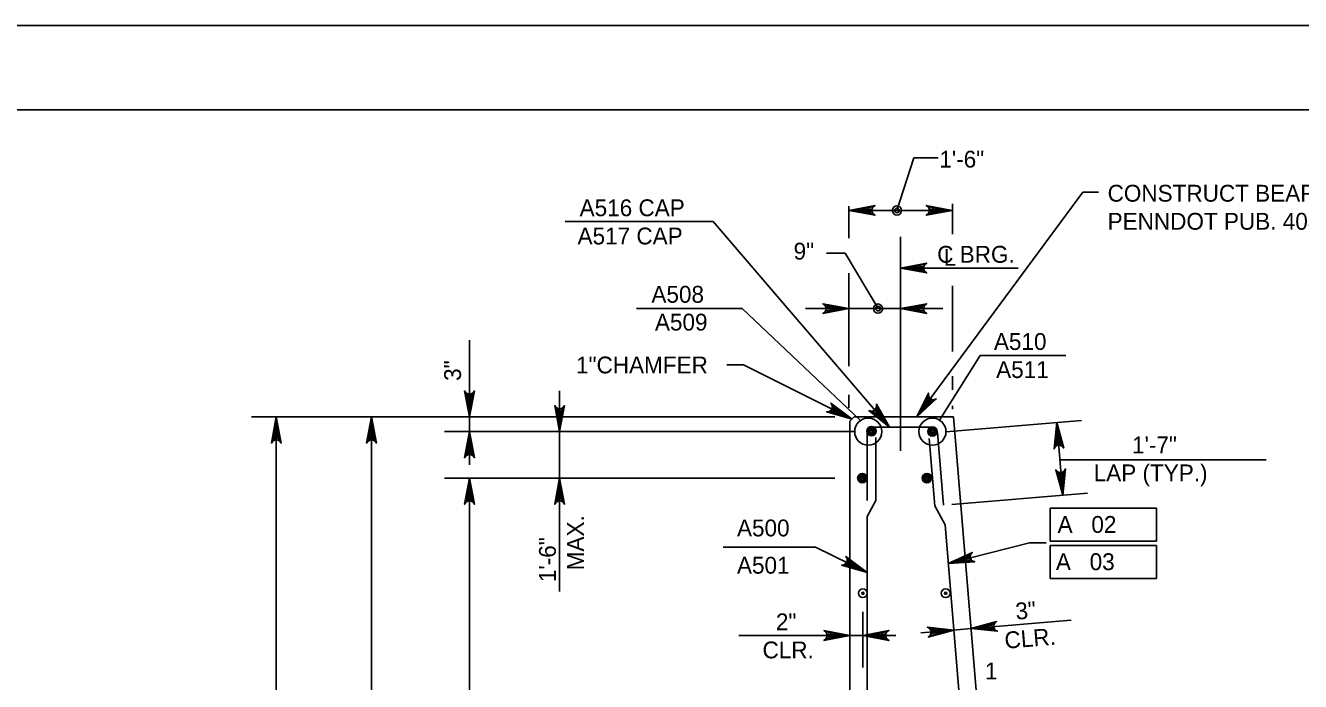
# Model space of a CAD drawing. Extents: x 638255 to 640306, y 296059 to 298435.
# Drawn here: x 638961.1 to 639188.3, y 298318.6 to 298435.5 of the extents above; entities that cross this region are included whole.
import ezdxf

# ---------------------------------------------------------------- set-up
doc = ezdxf.new("R2010")
doc.units = 0
for name, color, linetype in [('2', 7, 'Continuous'), ('3', 7, 'Continuous'), ('Level 3', 7, 'Continuous'), ('Level 4', 7, 'Continuous'), ('Level 5', 7, 'Continuous'), ('Level 9', 7, 'Continuous'), ('PLT-BNDY', 7, 'Continuous')]:
    doc.layers.add(name, color=color, linetype=linetype)

# ---------------------------------------------------------------- blocks, each defined once
blk = doc.blocks.new('B')
at = {"layer": '3'}
blk.add_circle((0, 0), 0.16, dxfattribs=at)
for start, end in [(0, 180), (180, 0)]:
    blk.add_arc((0, 0), 0.0391, start, end, dxfattribs=at)

msp = doc.modelspace()

# ---------------------------------------------------------------- linework, layer by layer
at = {"layer": '2'}
msp.add_line((638475.46, 298420.46), (639261.46, 298420.46), dxfattribs=at)
at = {"layer": 'Level 3'}
for p, q in [((639119.44, 298411.85), (639116.41, 298402.51)), ((639119.44, 298411.85), (639123.73, 298411.85)), ((639119.95, 298365.71), (639149.54, 298405.75)), ((639149.54, 298405.75), (639152.29, 298405.75)), ((639107.85, 298397.56), (639107.85, 298403.25)), ((639107.85, 298402.51), (639126.27, 298402.51)), ((639126.27, 298402.51), (639126.27, 298402.51)), ((639126.28, 298398.27), (639126.28, 298403.68)), ((639083.67, 298400.56), (639057.3, 298400.56)), ((639115.09, 298363.89), (639083.67, 298400.56)), ((639117.06, 298359.67), (639117.06, 298397.79)), ((639103.85, 298394.89), (639107.19, 298394.89)), ((639113.03, 298385.01), (639107.19, 298394.89)), ((639107.85, 298374.74), (639107.85, 298391.33)), ((639117.06, 298392.23), (639137.99, 298392.23)), ((639107.85, 298385.03), (639107.85, 298389.72)), ((639107.85, 298386.42), (639107.85, 298389.43)), ((639126.28, 298377.35), (639126.28, 298389.06)), ((639124.58, 298385.01), (639100.13, 298385.01)), ((639040.23, 298363.1), (639040.23, 298379.42)), ((639089.04, 298375), (639086.1, 298375)), ((639108.42, 298365.33), (639089.04, 298375)), ((639126.28, 298370.55), (639126.28, 298372.97)), ((639040.23, 298365.71), (639040.23, 298371.6)), ((639056.3, 298370.39), (639056.3, 298334.62)), ((639107.85, 298367.32), (639107.85, 298369.63)), ((639126.28, 298367.09), (639126.28, 298367.67)), ((639035.11, 298365.71), (639001.39, 298365.71)), ((639005.81, 298204.3), (639005.81, 298365.71)), ((639105.34, 298365.71), (639018.36, 298365.71)), ((639022.78, 298365.71), (639022.78, 298297.2)), ((639022.78, 298365.71), (639022.78, 298365.71)), ((639053.45, 298365.71), (639035.81, 298365.71)), ((639070.28, 298365.71), (639059.77, 298365.71)), ((639125.13, 298363.08), (639149.28, 298365.09)), ((639144.87, 298364.72), (639145.96, 298351.75)), ((639108.78, 298363.1), (639035.81, 298363.1)), ((639040.23, 298363.1), (639040.23, 298357.2)), ((639145.43, 298358.08), (639182.21, 298358.08)), ((639105.36, 298354.82), (639035.81, 298354.82)), ((639040.23, 298354.82), (639040.23, 298231.52)), ((639126.21, 298350.1), (639150.36, 298352.12)), ((639143.73, 298343.58), (639143.73, 298349.47)), ((639143.73, 298349.47), (639162.64, 298349.47)), ((639162.64, 298349.47), (639162.64, 298343.58)), ((639125.55, 298339.59), (639140.05, 298343.29)), ((639140.05, 298343.29), (639143, 298343.29)), ((639162.64, 298343.58), (639143.73, 298343.58)), ((639143.73, 298342.83), (639162.64, 298342.83)), ((639143.73, 298336.94), (639143.73, 298342.83)), ((639162.64, 298342.83), (639162.64, 298336.94)), ((639101.9, 298342.54), (639085.43, 298342.54)), ((639111.09, 298338.02), (639101.9, 298342.54)), ((639162.64, 298336.94), (639143.73, 298336.94)), ((639108.03, 298328.03), (639108.03, 298330.96)), ((639110.32, 298321.1), (639110.32, 298330.96)), ((639135.47, 298328.5), (639147.43, 298329.49)), ((639102.14, 298326.77), (639088.22, 298326.77)), ((639105.09, 298326.77), (639102.14, 298326.77)), ((639110.32, 298326.77), (639108.03, 298326.77)), ((639113.26, 298326.77), (639116.21, 298326.77)), ((639126.53, 298327.75), (639120.66, 298327.26)), ((639126.53, 298327.75), (639129.59, 298328.01)), ((639129.59, 298328.01), (639135.47, 298328.5)), ((639108.03, 298326.34), (639108.03, 298322.35)), ((639110.32, 298326.34), (639110.32, 298322.35))]:
    msp.add_line(p, q, dxfattribs=at)
for points in [[(639107.85, 298402.51), (639112.5, 298403.38), (639112.14, 298403.13), (639111.96, 298402.82), (639111.9, 298402.51), (639111.96, 298402.2), (639112.14, 298401.89), (639112.5, 298401.64), (639107.85, 298402.51), (639112.14, 298401.89), (639111.96, 298402.2), (639107.85, 298402.51), (639111.9, 298402.51), (639111.96, 298402.82), (639107.85, 298402.51), (639112.14, 298403.13)], [(639126.27, 298402.51), (639121.62, 298401.64), (639121.98, 298401.89), (639122.17, 298402.2), (639122.22, 298402.51), (639122.17, 298402.82), (639121.98, 298403.13), (639121.62, 298403.38), (639126.27, 298402.51), (639121.98, 298403.13), (639122.17, 298402.82), (639126.27, 298402.51), (639122.22, 298402.51), (639122.17, 298402.2), (639126.27, 298402.51), (639121.98, 298401.89)], [(639117.06, 298392.23), (639121.71, 298393.1), (639121.35, 298392.85), (639121.17, 298392.54), (639121.11, 298392.23), (639121.17, 298391.92), (639121.35, 298391.6), (639121.71, 298391.36), (639117.06, 298392.23), (639121.35, 298391.6), (639121.17, 298391.92), (639117.06, 298392.23), (639121.11, 298392.23), (639121.17, 298392.54), (639117.06, 298392.23), (639121.35, 298392.85)], [(639107.85, 298385.01), (639103.2, 298384.14), (639103.55, 298384.39), (639103.74, 298384.7), (639103.79, 298385.01), (639103.74, 298385.33), (639103.55, 298385.64), (639103.2, 298385.88), (639107.85, 298385.01), (639103.55, 298385.64), (639103.74, 298385.33), (639107.85, 298385.01), (639103.79, 298385.01), (639103.74, 298384.7), (639107.85, 298385.01), (639103.55, 298384.39)], [(639117.06, 298385.01), (639121.71, 298385.88), (639121.35, 298385.64), (639121.17, 298385.33), (639121.11, 298385.01), (639121.17, 298384.7), (639121.35, 298384.39), (639121.71, 298384.14), (639117.06, 298385.01), (639121.35, 298384.39), (639121.17, 298384.7), (639117.06, 298385.01), (639121.11, 298385.01), (639121.17, 298385.33), (639117.06, 298385.01), (639121.35, 298385.64)], [(639040.23, 298365.71), (639039.36, 298370.36), (639039.61, 298370), (639039.92, 298369.82), (639040.23, 298369.76), (639040.55, 298369.82), (639040.86, 298370), (639041.11, 298370.36), (639040.23, 298365.71), (639040.86, 298370), (639040.55, 298369.82), (639040.23, 298365.71), (639040.23, 298369.76), (639039.92, 298369.82), (639040.23, 298365.71), (639039.61, 298370)], [(639119.95, 298365.71), (639122.01, 298369.97), (639122, 298369.53), (639122.14, 298369.2), (639122.36, 298368.97), (639122.64, 298368.83), (639123, 298368.79), (639123.42, 298368.93), (639119.95, 298365.71), (639123, 298368.79), (639122.64, 298368.83), (639119.95, 298365.71), (639122.36, 298368.97), (639122.14, 298369.2), (639119.95, 298365.71), (639122, 298369.53)], [(639056.3, 298363.1), (639055.42, 298367.75), (639055.67, 298367.39), (639055.98, 298367.21), (639056.3, 298367.15), (639056.61, 298367.21), (639056.92, 298367.39), (639057.17, 298367.75), (639056.3, 298363.1), (639056.92, 298367.39), (639056.61, 298367.21), (639056.3, 298363.1), (639056.3, 298367.15), (639055.98, 298367.21), (639056.3, 298363.1), (639055.67, 298367.39)], [(639108.42, 298365.33), (639103.87, 298366.63), (639104.3, 298366.69), (639104.6, 298366.88), (639104.79, 298367.14), (639104.88, 298367.44), (639104.85, 298367.8), (639104.64, 298368.18), (639108.42, 298365.33), (639104.85, 298367.8), (639104.88, 298367.44), (639108.42, 298365.33), (639104.79, 298367.14), (639104.6, 298366.88), (639108.42, 298365.33), (639104.3, 298366.69)], [(639115.09, 298363.89), (639111.4, 298366.85), (639111.83, 298366.74), (639112.18, 298366.8), (639112.45, 298366.97), (639112.66, 298367.21), (639112.78, 298367.55), (639112.73, 298367.99), (639115.09, 298363.89), (639112.78, 298367.55), (639112.66, 298367.21), (639115.09, 298363.89), (639112.45, 298366.97), (639112.18, 298366.8), (639115.09, 298363.89), (639111.83, 298366.74)], [(639005.81, 298365.71), (639006.68, 298361.06), (639006.43, 298361.41), (639006.12, 298361.6), (639005.81, 298361.65), (639005.5, 298361.6), (639005.19, 298361.41), (639004.94, 298361.06), (639005.81, 298365.71), (639005.19, 298361.41), (639005.5, 298361.6), (639005.81, 298365.71), (639005.81, 298361.65), (639006.12, 298361.6), (639005.81, 298365.71), (639006.43, 298361.41)], [(639022.78, 298365.71), (639023.65, 298361.06), (639023.41, 298361.41), (639023.09, 298361.6), (639022.78, 298361.65), (639022.47, 298361.6), (639022.16, 298361.41), (639021.91, 298361.06), (639022.78, 298365.71), (639022.16, 298361.41), (639022.47, 298361.6), (639022.78, 298365.71), (639022.78, 298361.65), (639023.09, 298361.6), (639022.78, 298365.71), (639023.41, 298361.41)], [(639144.87, 298364.72), (639146.13, 298360.16), (639145.85, 298360.5), (639145.53, 298360.65), (639145.21, 298360.68), (639144.9, 298360.6), (639144.61, 298360.39), (639144.39, 298360.01), (639144.87, 298364.72), (639144.61, 298360.39), (639144.9, 298360.6), (639144.87, 298364.72), (639145.21, 298360.68), (639145.53, 298360.65), (639144.87, 298364.72), (639145.85, 298360.5)], [(639040.23, 298363.1), (639041.11, 298358.45), (639040.86, 298358.8), (639040.55, 298358.99), (639040.23, 298359.04), (639039.92, 298358.99), (639039.61, 298358.8), (639039.36, 298358.45), (639040.23, 298363.1), (639039.61, 298358.8), (639039.92, 298358.99), (639040.23, 298363.1), (639040.23, 298359.04), (639040.55, 298358.99), (639040.23, 298363.1), (639040.86, 298358.8)], [(639145.96, 298351.75), (639144.7, 298356.31), (639144.98, 298355.97), (639145.3, 298355.82), (639145.62, 298355.79), (639145.92, 298355.87), (639146.22, 298356.08), (639146.44, 298356.46), (639145.96, 298351.75), (639146.22, 298356.08), (639145.92, 298355.87), (639145.96, 298351.75), (639145.62, 298355.79), (639145.3, 298355.82), (639145.96, 298351.75), (639144.98, 298355.97)], [(639040.23, 298354.82), (639041.11, 298350.17), (639040.86, 298350.53), (639040.55, 298350.71), (639040.23, 298350.77), (639039.92, 298350.71), (639039.61, 298350.53), (639039.36, 298350.17), (639040.23, 298354.82), (639039.61, 298350.53), (639039.92, 298350.71), (639040.23, 298354.82), (639040.23, 298350.77), (639040.55, 298350.71), (639040.23, 298354.82), (639040.86, 298350.53)], [(639056.3, 298354.82), (639057.17, 298350.17), (639056.92, 298350.53), (639056.61, 298350.71), (639056.3, 298350.77), (639055.98, 298350.71), (639055.67, 298350.53), (639055.42, 298350.17), (639056.3, 298354.82), (639055.67, 298350.53), (639055.98, 298350.71), (639056.3, 298354.82), (639056.3, 298350.77), (639056.61, 298350.71), (639056.3, 298354.82), (639056.92, 298350.53)], [(639111.09, 298338.02), (639106.53, 298339.29), (639106.96, 298339.35), (639107.26, 298339.55), (639107.45, 298339.81), (639107.54, 298340.11), (639107.51, 298340.48), (639107.3, 298340.86), (639111.09, 298338.02), (639107.51, 298340.48), (639107.54, 298340.11), (639111.09, 298338.02), (639107.45, 298339.81), (639107.26, 298339.55), (639111.09, 298338.02), (639106.96, 298339.35)], [(639125.55, 298339.59), (639129.84, 298341.59), (639129.55, 298341.26), (639129.45, 298340.91), (639129.47, 298340.59), (639129.6, 298340.3), (639129.86, 298340.05), (639130.27, 298339.9), (639125.55, 298339.59), (639129.86, 298340.05), (639129.6, 298340.3), (639125.55, 298339.59), (639129.47, 298340.59), (639129.45, 298340.91), (639125.55, 298339.59), (639129.55, 298341.26)], [(639129.59, 298328.01), (639134.16, 298329.26), (639133.82, 298328.99), (639133.66, 298328.66), (639133.63, 298328.34), (639133.71, 298328.04), (639133.92, 298327.74), (639134.3, 298327.53), (639129.59, 298328.01), (639133.92, 298327.74), (639133.71, 298328.04), (639129.59, 298328.01), (639133.63, 298328.34), (639133.66, 298328.66), (639129.59, 298328.01), (639133.82, 298328.99)], [(639108.03, 298326.77), (639103.38, 298325.9), (639103.74, 298326.15), (639103.92, 298326.46), (639103.98, 298326.77), (639103.92, 298327.09), (639103.74, 298327.4), (639103.38, 298327.65), (639108.03, 298326.77), (639103.74, 298327.4), (639103.92, 298327.09), (639108.03, 298326.77), (639103.98, 298326.77), (639103.92, 298326.46), (639108.03, 298326.77), (639103.74, 298326.15)], [(639110.32, 298326.77), (639114.97, 298327.65), (639114.61, 298327.4), (639114.42, 298327.09), (639114.37, 298326.77), (639114.42, 298326.46), (639114.61, 298326.15), (639114.97, 298325.9), (639110.32, 298326.77), (639114.61, 298326.15), (639114.42, 298326.46), (639110.32, 298326.77), (639114.37, 298326.77), (639114.42, 298327.09), (639110.32, 298326.77), (639114.61, 298327.4)], [(639126.53, 298327.75), (639121.97, 298326.5), (639122.31, 298326.77), (639122.47, 298327.1), (639122.49, 298327.42), (639122.42, 298327.72), (639122.21, 298328.02), (639121.83, 298328.24), (639126.53, 298327.75), (639122.21, 298328.02), (639122.42, 298327.72), (639126.53, 298327.75), (639122.49, 298327.42), (639122.47, 298327.1), (639126.53, 298327.75), (639122.31, 298326.77)]]:
    msp.add_lwpolyline(points, dxfattribs=at)
for points in [[(639110.8, 298402.02), (639110.8, 298403), (639107.85, 298402.51)], [(639123.33, 298402.02), (639123.33, 298403), (639126.27, 298402.51)], [(639120.01, 298391.74), (639120.01, 298392.72), (639117.06, 298392.23)], [(639039.74, 298368.66), (639040.73, 298368.66), (639040.23, 298365.71)], [(639005.32, 298362.76), (639006.3, 298362.76), (639005.81, 298365.71)], [(639023.27, 298362.76), (639022.29, 298362.76), (639022.78, 298365.71)], [(639106, 298367.08), (639105.56, 298366.21), (639108.42, 298365.33)], [(639113.54, 298366.46), (639112.79, 298365.82), (639115.06, 298363.89)], [(639145.61, 298361.82), (639144.63, 298361.74), (639144.87, 298364.72)], [(639039.74, 298360.15), (639040.73, 298360.15), (639040.23, 298363.1)], [(639039.74, 298351.87), (639040.73, 298351.87), (639040.23, 298354.82)], [(639146.2, 298354.73), (639145.22, 298354.65), (639145.95, 298351.75)], [(639128.74, 298339.9), (639128.49, 298340.85), (639125.76, 298339.65)], [(639108.66, 298339.76), (639108.23, 298338.88), (639111.09, 298338.02)], [(639105.09, 298327.27), (639105.09, 298326.28), (639108.03, 298326.77)], [(639113.26, 298327.27), (639113.26, 298326.28), (639110.32, 298326.77)], [(639123.56, 298328), (639123.64, 298327.02), (639126.53, 298327.75)], [(639132.49, 298328.74), (639132.57, 298327.76), (639129.59, 298328.01)]]:
    msp.add_lwpolyline(points, close=True, dxfattribs=at)
for centre, radius in [((639116.41, 298402.51), 0.832), ((639116.41, 298402.51), 0.416), ((639113.03, 298385.01), 0.832), ((639113.03, 298385.01), 0.416)]:
    msp.add_circle(centre, radius, dxfattribs=at)
at = {"layer": 'Level 4'}
for p, q in [((639088.83, 298385.01), (639069.98, 298385.01)), ((639109.88, 298365.07), (639088.83, 298385.01)), ((639124.01, 298365.15), (639131.25, 298376.64)), ((639131.25, 298376.64), (639146.47, 298376.64))]:
    msp.add_line(p, q, dxfattribs=at)
for centre in [(639111.29, 298363.1), (639122.72, 298363.1)]:
    msp.add_circle(centre, 2.42, dxfattribs=at)
at = {"layer": 'Level 5'}
for p, q in [((639112.11, 298363.89), (639122.58, 298363.89)), ((639111.09, 298350.81), (639111.09, 298362.86)), ((639112.63, 298350.81), (639112.63, 298362.04)), ((639122.15, 298361.86), (639123.15, 298349.85)), ((639123.6, 298362.95), (639124.68, 298349.98)), ((639112.63, 298350.81), (639111.09, 298347.98)), ((639123.15, 298349.85), (639124.97, 298346.49)), ((639111.09, 298274.15), (639111.09, 298347.98)), ((639124.97, 298346.49), (639128.57, 298303.29))]:
    msp.add_line(p, q, dxfattribs=at)
for centre, radius in [((639111.87, 298363.19), 0.832), ((639111.87, 298363.19), 0.624), ((639111.87, 298363.19), 0.416), ((639111.87, 298363.19), 0.208), ((639122.72, 298363.1), 0.832), ((639122.72, 298363.1), 0.624), ((639122.72, 298363.1), 0.416), ((639122.72, 298363.1), 0.208), ((639110.23, 298354.82), 0.832), ((639110.23, 298354.82), 0.624), ((639110.23, 298354.82), 0.416), ((639110.23, 298354.82), 0.208), ((639121.74, 298354.82), 0.832), ((639121.74, 298354.82), 0.624), ((639121.74, 298354.82), 0.416), ((639121.74, 298354.82), 0.208)]:
    msp.add_circle(centre, radius, dxfattribs=at)
for centre, start, end in [((639112.11, 298362.86), 90, 180), ((639122.58, 298362.86), 4.7636, 90)]:
    msp.add_arc(centre, 1.02, start, end, dxfattribs=at)
at = {"layer": 'Level 9'}
for p, q in [((639108.03, 298364.94), (639108.8, 298365.71)), ((639108.8, 298365.71), (639126.45, 298365.71)), ((639126.45, 298365.71), (639137.85, 298228.95)), ((639108.03, 298267.34), (639108.03, 298364.94))]:
    msp.add_line(p, q, dxfattribs=at)
at = {"layer": 'PLT-BNDY'}
msp.add_lwpolyline([(638435.46, 298435.46), (639276.46, 298435.46), (639276.46, 297841.46), (638435.46, 297841.46)], close=True, dxfattribs=at)

# ---------------------------------------------------------------- block references
at = {"layer": 'Level 3', "xscale": 4.911876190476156, "yscale": 4.911876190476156, "rotation": 90}
for p in [(639110.32, 298334.3), (639125.08, 298334.3)]:
    msp.add_blockref('B', p, dxfattribs=at)

# ---------------------------------------------------------------- texts
at = {"layer": 'Level 3'}
for s, height, p in [('1\'-6"', 3, (639123.96, 298410.14)), ('CONSTRUCT BEARING AREAS AS PER', 3.0001, (639153.94, 298404.07)), ('A516 CAP', 3, (639059.86, 298401.48)), ('PENNDOT PUB. 408 1001.3 (k) 9.', 3.0001, (639153.94, 298399.07)), ('A517 CAP', 3, (639059.49, 298396.45)), ('9"', 3, (639097.99, 298393.75)), ('C BRG.', 3, (639123.57, 298393.19)), ('L', 3, (639124.73, 298392.64)), ('A508', 3, (639072.65, 298386.06)), ('A509', 3, (639073.28, 298381.11)), ('A510', 3, (639133.68, 298377.65)), ('1"CHAMFER', 3, (639059.22, 298373.47)), ('A511', 3, (639134.08, 298372.65)), ('1\'-7"', 3, (639158.3, 298359.23)), ('LAP (TYP.)', 3, (639151.46, 298354.24)), ('A500', 3, (639087.9, 298344.43)), ('A   02', 3, (639145.03, 298345.06)), ('A501', 3, (639087.9, 298337.79)), ('A   03', 3, (639144.72, 298338.42)), ('2"', 3, (639094.83, 298327.7)), ('CLR.', 3, (639092.45, 298322.7)), ('1', 3, (639132.07, 298318.95))]:
    msp.add_text(s, height=height, dxfattribs=at).set_placement(p)
for s, rotation, p in [('3"', 90, (639038.72, 298372.14)), ('MAX.', 90, (639060.62, 298338.39)), ('1\'-6"', 90, (639055.62, 298336.29)), ('3"', 4.7636, (639137.65, 298329.58)), ('CLR.', 4.7636, (639135.7, 298324.4))]:
    msp.add_text(s, height=3, rotation=rotation, dxfattribs=at).set_placement(p)

doc.saveas('drawing.dxf')
